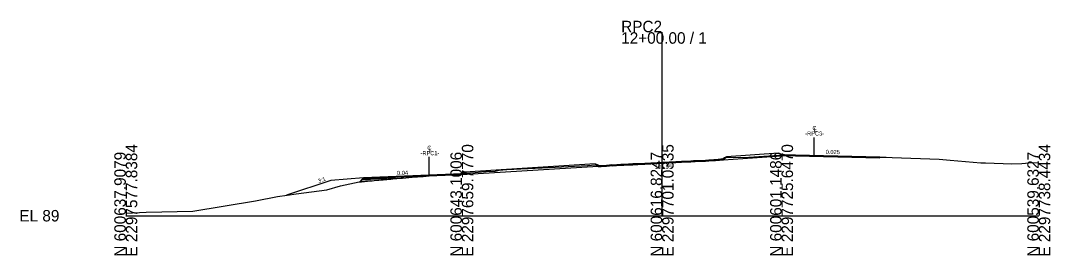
# Model space of a CAD drawing. Extents: x 2124 to 2376, y -10 to 1517.
# Drawn here: x 2124.3 to 2375.9, y 990.3 to 1047.7 of the extents above; entities that cross this region are included whole.
import ezdxf

# ---------------------------------------------------------------- set-up
doc = ezdxf.new("R2010")
doc.units = 0
for name, color, linetype in [('Exist Cross Section Cell', 7, 'Continuous'), ('Exist XS Center Line Elevation Label', 7, 'Continuous'), ('Exist XS Ground Line', 7, 'Continuous'), ('Prop CMT Pvmt Course 3 Wedge', 7, 'Continuous'), ('Prop CMT Pvmt Surface', 7, 'Continuous'), ('Prop CMT Pvmt Surface Overlay', 7, 'Continuous'), ('Prop CMT Shld Paved Course 1', 7, 'Continuous'), ('Prop CMT Shld Paved Course 2', 7, 'Continuous'), ('Prop CMT Slope Grass', 7, 'Continuous'), ('Prop Dimension', 7, 'Continuous'), ('Prop XS Earthwork Shape', 7, 'Continuous'), ('Prop XS Label Text', 7, 'Continuous'), ('Prop XS SE Text', 7, 'Continuous'), ('Prop XS Side Slope Text', 7, 'Continuous')]:
    doc.layers.add(name, color=color, linetype=linetype)

msp = doc.modelspace()

# ---------------------------------------------------------------- linework, layer by layer
at = {"layer": 'Exist Cross Section Cell'}
for p, q in [((2281.02, 1000), (2281.02, 1044.82)), ((2150, 1000), (2232.1, 1000)), ((2232.1, 1000), (2281.02, 1000)), ((2281.02, 1000), (2310.2, 1000)), ((2310.2, 1000), (2373.03, 1000))]:
    msp.add_line(p, q, dxfattribs=at)
at = {"layer": 'Exist XS Ground Line'}
msp.add_lwpolyline([(2150, 1000.66), (2154.98, 1000.85), (2166.38, 1001.14), (2181.7, 1003.66), (2187.1, 1004.66), (2189.46, 1005.04), (2191.64, 1005.31), (2199.14, 1006.3), (2202.44, 1007.33), (2205.91, 1008.02), (2207.02, 1008.25), (2207.58, 1008.3), (2208.32, 1008.36), (2209.78, 1008.49), (2210.23, 1008.55), (2210.7, 1008.63), (2211.83, 1008.7), (2212.29, 1008.73), (2212.9, 1008.79), (2214.79, 1008.96), (2215.26, 1009), (2217.3, 1009.18), (2217.61, 1009.21), (2219.97, 1009.42), (2222.61, 1009.62), (2224.81, 1009.79), (2227.32, 1009.98), (2229.39, 1010.15), (2229.82, 1010.18), (2231.75, 1010.33), (2232.37, 1010.37), (2232.99, 1010.4), (2233.82, 1010.43), (2234.18, 1010.47), (2235.33, 1010.59), (2236.86, 1010.7), (2238.03, 1010.77), (2240.22, 1010.91), (2240.85, 1011.05), (2241.22, 1011.16), (2243.06, 1011.26), (2251.71, 1011.67), (2262.81, 1012.28), (2264.74, 1012.41), (2265.39, 1012.13), (2265.74, 1012.15), (2266.1, 1012.17), (2267.42, 1012.25), (2268.17, 1012.3), (2268.54, 1012.35), (2268.91, 1012.32), (2270.9, 1012.44), (2271.68, 1012.48), (2273.86, 1012.59), (2275.11, 1012.65), (2276.83, 1012.74), (2279.78, 1012.88), (2280.86, 1012.93), (2281.17, 1012.96), (2281.59, 1012.98), (2282.76, 1013.05), (2284.41, 1013.12), (2285.72, 1013.17), (2288.01, 1013.3), (2288.68, 1013.35), (2289.07, 1013.36), (2291.65, 1013.48), (2292.45, 1013.54), (2293.68, 1013.58), (2294.08, 1013.61), (2296.01, 1013.81), (2296.71, 1014.27), (2301.01, 1014.25), (2309.55, 1014.83), (2310.2, 1014.89), (2310.88, 1014.94), (2311.55, 1014.7), (2311.96, 1014.71), (2313.32, 1014.71), (2313.92, 1014.7), (2314.85, 1014.69), (2316.48, 1014.66), (2319.3, 1014.61), (2321.59, 1014.58), (2323.3, 1014.54), (2324.14, 1014.53), (2325.41, 1014.52), (2326.69, 1014.51), (2328.63, 1014.47), (2329.25, 1014.46), (2331.8, 1014.37), (2333.87, 1014.34), (2334.35, 1014.32), (2335.79, 1014.29), (2337.25, 1014.21), (2348.68, 1013.81), (2351.42, 1013.57), (2358.88, 1012.92), (2360.03, 1012.88), (2366.45, 1012.66), (2368.91, 1012.73), (2371.46, 1012.97), (2373.03, 1012.88)], dxfattribs=at)
at = {"layer": 'Prop CMT Pvmt Course 3 Wedge'}
for p in [(2207.59, 1008.75), (2209.89, 1008.5)]:
    msp.add_line(p, (2207.23, 1008.4), dxfattribs=at)
at = {"layer": 'Prop CMT Pvmt Surface'}
for p, q in [((2334.2, 1014.3), (2310.2, 1014.9)), ((2334.2, 1014.05), (2310.2, 1014.65)), ((2216.32, 1009.1), (2207.58, 1008.75)), ((2232.1, 1009.98), (2207.84, 1009.01)), ((2232.1, 1010.23), (2208.1, 1009.27))]:
    msp.add_line(p, q, dxfattribs=at)
for points in [[(2265.39, 1012.26), (2265.74, 1012.27), (2266.1, 1012.29), (2267.42, 1012.37), (2268.17, 1012.42), (2268.54, 1012.48), (2268.91, 1012.45), (2270.9, 1012.57), (2271.68, 1012.61), (2273.86, 1012.72), (2275.11, 1012.78), (2276.83, 1012.86), (2279.78, 1013.01), (2280.86, 1013.06), (2281.17, 1013.08), (2281.59, 1013.11), (2282.76, 1013.18), (2284.41, 1013.24), (2285.72, 1013.3), (2288.01, 1013.43), (2288.68, 1013.47), (2289.07, 1013.49), (2291.65, 1013.6), (2292.45, 1013.66), (2293.68, 1013.71), (2294.08, 1013.73), (2296.01, 1013.94)], [(2265.39, 1012.01), (2265.74, 1012.02), (2266.1, 1012.04), (2267.42, 1012.12), (2268.17, 1012.17), (2268.54, 1012.23), (2268.91, 1012.2), (2270.9, 1012.32), (2271.68, 1012.36), (2273.86, 1012.47), (2275.11, 1012.53), (2276.83, 1012.61), (2279.78, 1012.76), (2280.86, 1012.81), (2281.17, 1012.83), (2281.59, 1012.86), (2282.76, 1012.93), (2284.41, 1012.99), (2285.72, 1013.05), (2288.01, 1013.18), (2288.68, 1013.22), (2289.07, 1013.24), (2291.65, 1013.35), (2292.45, 1013.41), (2293.68, 1013.46), (2294.08, 1013.48), (2296.01, 1013.69)]]:
    msp.add_lwpolyline(points, dxfattribs=at)
at = {"layer": 'Prop CMT Pvmt Surface Overlay'}
for p, q in [((2334.2, 1014.3), (2310.2, 1014.9)), ((2334.2, 1014.05), (2310.2, 1014.65)), ((2232.1, 1009.98), (2207.84, 1009.01)), ((2232.1, 1010.23), (2208.1, 1009.27))]:
    msp.add_line(p, q, dxfattribs=at)
for points in [[(2265.39, 1012.26), (2265.74, 1012.27), (2266.1, 1012.29), (2267.42, 1012.37), (2268.17, 1012.42), (2268.54, 1012.48), (2268.91, 1012.45), (2270.9, 1012.57), (2271.68, 1012.61), (2273.86, 1012.72), (2275.11, 1012.78), (2276.83, 1012.86), (2279.78, 1013.01), (2280.86, 1013.06), (2281.17, 1013.08), (2281.59, 1013.11), (2282.76, 1013.18), (2284.41, 1013.24), (2285.72, 1013.3), (2288.01, 1013.43), (2288.68, 1013.47), (2289.07, 1013.49), (2291.65, 1013.6), (2292.45, 1013.66), (2293.68, 1013.71), (2294.08, 1013.73), (2296.01, 1013.94)], [(2265.39, 1012.01), (2265.74, 1012.02), (2266.1, 1012.04), (2267.42, 1012.12), (2268.17, 1012.17), (2268.54, 1012.23), (2268.91, 1012.2), (2270.9, 1012.32), (2271.68, 1012.36), (2273.86, 1012.47), (2275.11, 1012.53), (2276.83, 1012.61), (2279.78, 1012.76), (2280.86, 1012.81), (2281.17, 1012.83), (2281.59, 1012.86), (2282.76, 1012.93), (2284.41, 1012.99), (2285.72, 1013.05), (2288.01, 1013.18), (2288.68, 1013.22), (2289.07, 1013.24), (2291.65, 1013.35), (2292.45, 1013.41), (2293.68, 1013.46), (2294.08, 1013.48), (2296.01, 1013.69)]]:
    msp.add_lwpolyline(points, dxfattribs=at)
at = {"layer": 'Prop CMT Shld Paved Course 1'}
msp.add_lwpolyline([(2208.1, 1009.27), (2207.84, 1009.01)], dxfattribs=at)
at = {"layer": 'Prop CMT Shld Paved Course 2'}
msp.add_line((2216.32, 1009.1), (2207.58, 1008.75), dxfattribs=at)
msp.add_lwpolyline([(2207.85, 1009.01), (2207.58, 1008.75)], dxfattribs=at)
at = {"layer": 'Prop CMT Slope Grass'}
for p, q in [((2208.1, 1009.27), (2200.1, 1008.63)), ((2208.1, 1009.27), (2207.23, 1008.4)), ((2200.1, 1008.63), (2189.24, 1005.01)), ((2207.23, 1008.4), (2209.89, 1008.5))]:
    msp.add_line(p, q, dxfattribs=at)
at = {"layer": 'Prop Dimension'}
for p, q in [((2296.01, 1013.69), (2310.2, 1014.65)), ((2296.76, 1014.35), (2296.01, 1014.1)), ((2296.01, 1013.69), (2296.01, 1014.1)), ((2309.45, 1015.31), (2296.76, 1014.35)), ((2309.45, 1015.31), (2310.2, 1015.06)), ((2310.2, 1014.65), (2310.2, 1015.06)), ((2265.39, 1012.01), (2232.1, 1009.98)), ((2264.64, 1012.67), (2232.85, 1010.64)), ((2264.64, 1012.67), (2265.39, 1012.42)), ((2265.39, 1012.01), (2265.39, 1012.42)), ((2232.85, 1010.64), (2232.1, 1010.39)), ((2232.1, 1009.98), (2232.1, 1010.39))]:
    msp.add_line(p, q, dxfattribs=at)
at = {"layer": 'Prop XS Earthwork Shape'}
msp.add_lwpolyline([(2199.14, 1006.3), (2202.44, 1007.33), (2205.91, 1008.02), (2207.02, 1008.25), (2207.58, 1008.3), (2208.32, 1008.36), (2209.78, 1008.49), (2209.89, 1008.5), (2207.23, 1008.4), (2208.1, 1009.27), (2200.1, 1008.63), (2189.24, 1005.01), (2189.46, 1005.04), (2191.64, 1005.31)], close=True, dxfattribs=at)
at = {"layer": 'Prop XS Label Text'}
for p, q in [((2318.2, 1014.7), (2318.2, 1019.14)), ((2224.1, 1009.91), (2224.1, 1014.35))]:
    msp.add_line(p, q, dxfattribs=at)

# ---------------------------------------------------------------- texts
at = {"layer": 'Exist Cross Section Cell'}
for s, p in [('RPC2', (2271.02, 1044.82)), ('12+00.00 / 1', (2271.02, 1042.02)), ('EL 89', (2124, 998.6))]:
    msp.add_text(s, height=2.8, dxfattribs=at).set_placement(p)
for s, p in [('E 2297577.8384', (2152.8, 990)), ('E 2297659.7770', (2234.9, 990)), ('E 2297701.0335', (2283.82, 990)), ('E 2297725.6470', (2313, 990)), ('E 2297738.4434', (2375.83, 990)), ('N 600637.9079', (2150, 990)), ('N 600643.1006', (2232.1, 990)), ('N 600616.8247', (2281.02, 990)), ('N 600601.1486', (2310.2, 990)), ('N 600539.6327', (2373.03, 990))]:
    msp.add_text(s, height=2.8, rotation=90, dxfattribs=at).set_placement(p)
at = {"layer": 'Exist XS Center Line Elevation Label'}
msp.add_text('101.95', height=1, dxfattribs=at).set_placement((2279.22, 1011.45))
at = {"layer": 'Prop XS Label Text'}
for s, p in [('C', (2317.75, 1020.88)), ('L', (2318.03, 1020.55)), ('-RPC3-', (2315.98, 1019.57)), ('C', (2223.66, 1016.09)), ('L', (2223.93, 1015.76)), ('-RPC1-', (2222.01, 1014.78))]:
    msp.add_text(s, height=1, dxfattribs=at).set_placement(p)
at = {"layer": 'Prop XS SE Text'}
for s, rotation, p in [('0.025', 359.0101, (2320.97, 1015.1)), ('0.04', 0.8783, (2216.27, 1009.95))]:
    msp.add_text(s, height=1, rotation=rotation, dxfattribs=at).set_placement(p)
at = {"layer": 'Prop XS Side Slope Text'}
msp.add_text('3:1', height=1, rotation=20.6597, dxfattribs=at).set_placement((2197.14, 1007.95))

doc.saveas('drawing.dxf')
